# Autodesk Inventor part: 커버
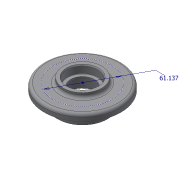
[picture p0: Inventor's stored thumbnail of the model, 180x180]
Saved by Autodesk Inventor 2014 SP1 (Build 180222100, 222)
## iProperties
Company: M-DU
Created: 2014-10
Part Number: 커버
Material: 일반
Document SubType Name: Modeling
Designer: KYOUNG IL JANG
Density: 1 g/cm^3
Appearance: 기본값
Author: KYOUNG IL JANG
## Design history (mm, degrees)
node "작업 평면1"
sketch "스케치1"
  geometry: C1 r 40 at (0, 0) reference; 1 further point
extrude "돌출1" new body sketch "스케치1" distance "d0" = 7; taper "d1" = 0 deg
sketch "스케치2"
  geometry: C1 r 27 at (0, 0) reference; 1 further point
extrude "돌출2" join sketch "스케치2" distance "d2" = 1; taper "d3" = 0 deg
sketch "스케치3"
  geometry: C1 r 27 at (0, 0) reference; C2 r 20 at (0, 0) reference; 1 further point
extrude "돌출3" join sketch "스케치3" distance "d4" = 12; taper "d5" = 0 deg
sketch "스케치4"
  geometry: C1 r 40 at (0, 0) reference; C2 r 20 at (0, 0); 1 further point
  constraints: 1 centre point
  dimensions: "d7" = 20 radial gap between concentric circles of C2 C1
extrude "돌출4" join sketch "스케치4" distance "d8" = 5; taper "d9" = 0 deg
hole "구멍1" diameter "d12" = 25; stored, may be unused: countersink angle "d16" = 90 deg, drill point angle "d18" = 118 deg; dims "d10" = 10, "d11" = 10, "d13" = 6, "d14" = 32, "d15" = 8.3, "d17" = 8
fillet "모깎기1" dims "d6" = 0.3
chamfer "모따기1" distance "d20" = 1; stored, may be unused: second distance "d21" = 2, angle "d22" = 45 deg
chamfer "모따기2" distance "d23" = 1.2; stored, may be unused: second distance "d24" = 2, angle "d25" = 30 deg
sketch "스케치5"
  geometry: C1 r 17 at (0, 0); 1 further point
  constraints: 1 centre point, 1 coincident
  dimensions: "d26" = 34 diameter of C1
extrude "돌출5" cut sketch "스케치5" distance "d27" = 3; taper "d28" = 0 deg
fillet "모깎기2" dims "d19" = 3
sketch "스케치6" dims "d29" = 65
  geometry: 3 further points
  constraints: 2 horizontal alignment, 1 coincident, 2 other
hole "구멍2" sketch "스케치6" at (32.5, 0) diameter "d30" = 4.5; stored, may be unused: countersink angle "d34" = 90 deg, drill point angle "d36" = 118 deg; dims "d31" = 6, "d32" = 8, "d33" = 4.4, "d35" = 8
node "솔리드1"
pattern_circular "원형 패턴1" dims angle "d38" = 360 deg
node "참조3"
node "참조4"
node "참조5"
